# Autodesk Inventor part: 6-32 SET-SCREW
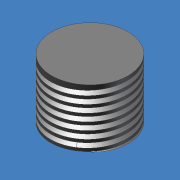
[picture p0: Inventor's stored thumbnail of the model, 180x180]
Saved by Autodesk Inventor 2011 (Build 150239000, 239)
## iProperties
Created: 2007-08
Part Number: 6-32 SET-SCREW
Document SubType Name: Modeling
Density: 1 g/cm^3
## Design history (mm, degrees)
feature "Base1"
body "Solid1"
